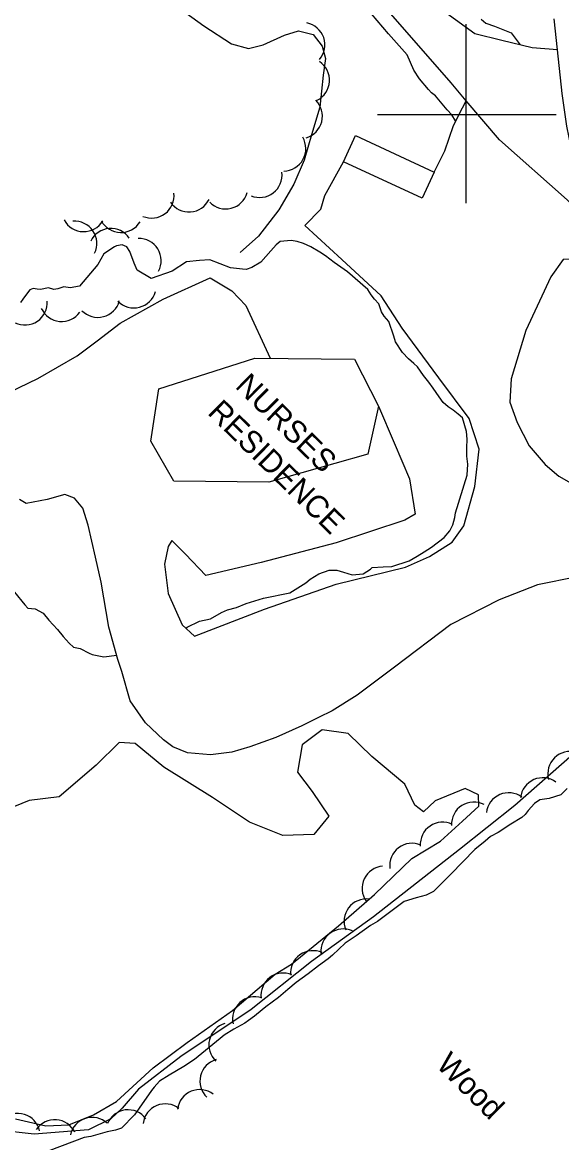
# Model space of a CAD drawing. Extents: x 642515 to 647219, y 6080136 to 6084356.
# Drawn here: x 643540.5 to 643612.9, y 6081462 to 6081612.4 of the extents above; entities that cross this region are included whole.
import ezdxf

# ---------------------------------------------------------------- set-up
doc = ezdxf.new("R2010")
doc.units = 0
for name, color, linetype in [('Level 19', 7, 'Continuous'), ('Level 2', 7, 'Continuous'), ('Level 21', 7, 'Continuous'), ('Level 31', 7, 'Continuous'), ('Level 4', 7, 'Continuous'), ('Level 44', 7, 'Continuous'), ('Level 61', 7, 'Continuous')]:
    doc.layers.add(name, color=color, linetype=linetype)

msp = doc.modelspace()

# ---------------------------------------------------------------- linework, layer by layer
at = {"layer": 'Level 19'}
for points in [[(643595.76, 6081592.33), (643597.18, 6081595.17), (643598.37, 6081598.59), (643599.58, 6081600.93), (643600.07, 6081601.9)], [(643588.29, 6081560.9), (643590.39, 6081555.97), (643592.44, 6081551.16), (643593.2, 6081546.42), (643591.8, 6081545.6), (643582.59, 6081542.57), (643572.51, 6081539.93), (643565.07, 6081538.15), (643562.38, 6081541.03), (643560.53, 6081542.88), (643560.02, 6081542.04), (643559.54, 6081539.67), (643560.04, 6081535.76), (643561.93, 6081531.54), (643563.56, 6081530.03), (643572.99, 6081533.64), (643582.59, 6081537.02), (643591.91, 6081539.29), (643595.12, 6081540.72), (643598.17, 6081542.65), (643599.72, 6081544.85), (643601.22, 6081550.11), (643601.82, 6081555.11), (643600.46, 6081559.25), (643596.39, 6081564.7), (643591.48, 6081571.35), (643588.65, 6081575.72), (643583.37, 6081580.57), (643578.4, 6081585.15), (643580.55, 6081587.35), (643581.07, 6081589.16), (643583.57, 6081593.71)], [(643618.02, 6081580.18), (643615.49, 6081580.74), (643613.08, 6081580.58), (643611.43, 6081578.25), (643608.07, 6081571.06), (643606.09, 6081564.56), (643605.93, 6081561.44), (643606.92, 6081558.69), (643608.5, 6081555.57), (643610.68, 6081553.05), (643612.51, 6081551.52), (643616.53, 6081549.21), (643619.17, 6081548.25), (643621.21, 6081547.99), (643624.04, 6081548.38), (643628.44, 6081549.43), (643630.6, 6081550.34), (643632.99, 6081551.81)], [(643537.52, 6081562.18), (643542.51, 6081564.6), (643547.81, 6081567.65), (643550.49, 6081569.68), (643553.6, 6081572.02), (643559.38, 6081575.26), (643565.66, 6081578.13), (643568.59, 6081576.39), (643570.45, 6081574.39), (643573.74, 6081567.33)], [(643614.95, 6081537.99), (643609.62, 6081536.91), (643604.48, 6081534.91), (643598.01, 6081531.58), (643590.42, 6081525.84), (643585.43, 6081522.12), (643582.06, 6081520), (643580.23, 6081519.12), (643577.97, 6081518), (643574.48, 6081516.44), (643571.02, 6081515.16), (643568.57, 6081514.43), (643565.7, 6081514.08), (643562.62, 6081514.36), (643560.67, 6081515.16), (643559.4, 6081516.12), (643557, 6081518.38), (643554.91, 6081521.34), (643553.8, 6081525.26), (643553.29, 6081526.91), (643552.08, 6081531.23), (643551.03, 6081537.28), (643550.25, 6081540.61), (643549.28, 6081544.93), (643548.56, 6081547.22), (643547.47, 6081548.55), (643546.15, 6081549.03), (643543.78, 6081548.39), (643540.96, 6081547.84), (643540.08, 6081548.38)]]:
    msp.add_lwpolyline(points, dxfattribs=at)
at = {"layer": 'Level 2'}
for points in [[(643598.65, 6081599.13), (643598.61, 6081599.18), (643598.11, 6081599.99), (643597.5, 6081600.67), (643595.93, 6081602.58), (643595.38, 6081602.98), (643594.99, 6081603.4), (643593.77, 6081604.85), (643593.04, 6081606), (643592.14, 6081608.07), (643589.62, 6081610.88), (643586.57, 6081614.45)], [(643602.06, 6081612.86), (643602.7, 6081612.3), (643603.85, 6081611.9), (643606.08, 6081611), (643607.29, 6081609.39)], [(643591.51, 6081568.1), (643590.57, 6081569.52), (643590.35, 6081570.31), (643589.65, 6081572.27), (643589.04, 6081572.96), (643588.68, 6081573.57), (643588.33, 6081574.64), (643587.76, 6081575.28), (643587.28, 6081575.85), (643586.83, 6081576.54), (643584.1, 6081578.93), (643582.32, 6081580.18), (643581.14, 6081581.07), (643580.38, 6081581.58), (643579.2, 6081582.3), (643578.21, 6081582.72), (643577.35, 6081583.02), (643576.54, 6081583.13), (643575.06, 6081582.99), (643574.53, 6081582.55), (643573.82, 6081581.74), (643572.48, 6081580.21), (643571.28, 6081579.52), (643570.49, 6081579.23), (643570.01, 6081579.28), (643568.39, 6081579.49), (643565.62, 6081580.55), (643564.26, 6081580.46), (643562.51, 6081580.26), (643560.58, 6081579.01), (643557.76, 6081578.02), (643555.87, 6081579.14), (643555.45, 6081580.11), (643554.9, 6081581.65), (643554.49, 6081582.3), (643553.87, 6081582.54), (643553.08, 6081582.41), (643552.81, 6081582.27), (643551.38, 6081581.33), (643550.6, 6081579.91), (643548.14, 6081577.02), (643546.87, 6081576.77), (643546.02, 6081576.91), (643545.19, 6081576.66), (643544.68, 6081576.58), (643543.94, 6081576.78), (643542.87, 6081576.58), (643542.42, 6081576.59), (643541.9, 6081576.68), (643541.46, 6081576.53), (643541.02, 6081575.94), (643540.51, 6081575.26)], [(643540.51, 6081575.26), (643540.18, 6081574.8)], [(643562.41, 6081531.1), (643562.6, 6081531.21), (643564.23, 6081532.04), (643565.7, 6081532.34), (643567.21, 6081533.2), (643567.98, 6081533.57), (643569.21, 6081533.86), (643570.5, 6081534.39), (643572.82, 6081535.14), (643576.35, 6081535.82), (643578.51, 6081537.17), (643579.12, 6081537.69), (643580.27, 6081538.41), (643581.65, 6081538.87), (643582.69, 6081538.86), (643583.6, 6081538.6), (643584.74, 6081538.27), (643586.22, 6081538.41), (643587.19, 6081539), (643587.45, 6081539.22), (643588.89, 6081539.31), (643590.09, 6081539.39), (643592.41, 6081540.15), (643593.46, 6081540.74), (643594.42, 6081541.33), (643595.42, 6081541.96), (643597.1, 6081543.28), (643597.88, 6081544.17), (643598.27, 6081544.96), (643598.53, 6081545.94), (643598.64, 6081546.59), (643600.19, 6081551.64), (643600.28, 6081553.13), (643600.13, 6081554.17), (643600.14, 6081555.29), (643600.18, 6081556.46), (643600.11, 6081557.5), (643599.54, 6081559.35), (643598.98, 6081559.84), (643598.3, 6081560.35), (643597.63, 6081560.79), (643596.95, 6081561.39), (643596.41, 6081562.16), (643595.61, 6081563.31), (643595.03, 6081564.11), (643594.33, 6081565.03), (643593.53, 6081566.18), (643593.01, 6081566.63), (643592.33, 6081567.23), (643591.51, 6081568.1)], [(643539.37, 6081535.92), (643540.77, 6081534.25), (643541.2, 6081533.8), (643542.17, 6081533.7), (643543.22, 6081533.09), (643544.01, 6081532.17), (643545.18, 6081530.93), (643545.93, 6081529.97), (643546.75, 6081529.1), (643547.31, 6081528.54), (643548.21, 6081528.36), (643549.41, 6081527.75), (643549.83, 6081527.54), (643551.38, 6081527.24), (643553.13, 6081527.47)], [(643550.01, 6081465.75), (643553.11, 6081467.56), (643558.03, 6081472.07), (643562.58, 6081475.46), (643568.68, 6081479.77), (643574.38, 6081484.65), (643576.58, 6081485.99), (643582.9, 6081491.15), (643587.76, 6081495.33), (643592.74, 6081500.16), (643596.6, 6081502.51), (643599.55, 6081505.19), (643601.75, 6081507.19), (643601.73, 6081508.71), (643599.9, 6081509.56), (643595.91, 6081507.93), (643594.32, 6081506.46), (643593.14, 6081507.34), (643591.82, 6081510.15), (643587.39, 6081513.88), (643584.21, 6081516.96), (643580.72, 6081517.45), (643578.05, 6081515.43), (643577.41, 6081511.77), (643579.35, 6081509.17), (643581.59, 6081505.86), (643579.58, 6081503.39), (643575.41, 6081503.28), (643570.95, 6081505.07), (643565.98, 6081508.36), (643559.44, 6081512.43), (643555.61, 6081515.63), (643553.43, 6081515.73), (643550.34, 6081512.71), (643545.4, 6081508.45), (643541.34, 6081507.94), (643536.41, 6081505.93)], [(643613.63, 6081509.56), (643612.76, 6081508.74), (643611.19, 6081508.24), (643609.95, 6081508.03), (643609.22, 6081507.54), (643608.4, 6081506.61), (643608, 6081506.06), (643607.54, 6081505.7), (643606.07, 6081504.8), (643604.34, 6081503.68), (643603.33, 6081503.14), (643602.61, 6081502.48), (643601.2, 6081501.39), (643598.01, 6081498.08), (643595.67, 6081495.76), (643594.7, 6081495.25)], [(643594.7, 6081495.25), (643593.32, 6081494.88), (643591.71, 6081494.41), (643588.15, 6081491.72), (643587.22, 6081491.18), (643585.27, 6081489.8), (643583.8, 6081488.82), (643582.1, 6081487.22), (643581.5, 6081486.7), (643580.23, 6081485.77), (643578.82, 6081484.67), (643577.21, 6081483.52), (643576.11, 6081482.6), (643574.85, 6081481.52), (643573.17, 6081480.28), (643572.64, 6081479.84), (643571.61, 6081479.01), (643570.8, 6081478.43), (643570.34, 6081478.08), (643568.87, 6081477.26), (643567.56, 6081476.45), (643567.03, 6081476.01), (643563.56, 6081473.17), (643562.14, 6081472.23), (643560.16, 6081471.1), (643558.85, 6081470.29), (643558.14, 6081469.48), (643557.81, 6081469.01), (643556.12, 6081466.65), (643555.5, 6081465.76), (643553.77, 6081463.96), (643552.94, 6081463.71), (643551.83, 6081463.47), (643549.63, 6081462.84), (643548.75, 6081462.7), (643542.48, 6081460.36)], [(643539.52, 6081465.22), (643543.6, 6081464.28), (643546.68, 6081464.44), (643550.01, 6081465.75)]]:
    msp.add_lwpolyline(points, dxfattribs=at)
at = {"layer": 'Level 21'}
for points in [[(643616.32, 6081586.09), (643616.32, 6081586.09), (643613.62, 6081588.61), (643604.55, 6081596.63), (643600.07, 6081601.9), (643598.04, 6081604.29), (643589.94, 6081613.58)], [(643612.33, 6081608.72), (643608.93, 6081608.98), (643604.83, 6081610), (643601.23, 6081610.88), (643597.34, 6081613.69)], [(643635.25, 6081548.28), (643632.99, 6081551.81), (643629.41, 6081557.4), (643623.45, 6081567.23), (643619.32, 6081576.06), (643618.02, 6081580.18), (643617.28, 6081582.53), (643616.32, 6081586.09), (643615.15, 6081590.89), (643613.56, 6081598.48), (643612.95, 6081602.87), (643612.33, 6081608.72), (643611.89, 6081612.88)]]:
    msp.add_lwpolyline(points, dxfattribs=at)
at = {"layer": 'Level 31'}
for points in [[(643594.14, 6081588.83), (643583.57, 6081593.71), (643585.19, 6081597.22), (643595.76, 6081592.33), (643594.14, 6081588.83)], [(643586.86, 6081554.46), (643573.54, 6081550.7), (643560.78, 6081550.82), (643557.7, 6081556.22), (643558.78, 6081563.24), (643571.65, 6081567.36), (643585.04, 6081567.21), (643588.29, 6081560.9), (643586.86, 6081554.46)]]:
    msp.add_lwpolyline(points, dxfattribs=at)
at = {"layer": 'Level 4'}
for points in [[(643561.6, 6081614.26), (643564.82, 6081611.97), (643568.53, 6081609.55), (643570.83, 6081608.9), (643572.77, 6081609.39), (643575.67, 6081610.71), (643577.53, 6081611.28), (643579.5, 6081610.77), (643580.73, 6081609.23), (643581.16, 6081607.57), (643580.87, 6081605.33), (643580.42, 6081601.02), (643579.3, 6081597.32), (643578.31, 6081593.94), (643576.91, 6081590.7), (643574.88, 6081587.26), (643572.17, 6081583.73), (643569.7, 6081581.51)], [(643614.35, 6081514.09), (643606.58, 6081507.28), (643599.15, 6081501.38), (643587.62, 6081492.35), (643579.28, 6081486.36), (643571.2, 6081479.89), (643561.75, 6081473.58), (643556.03, 6081469.21), (643553.87, 6081466.65), (643552.31, 6081465.22), (643549.35, 6081463.73), (643542.05, 6081463.16), (643537.22, 6081463.69)]]:
    msp.add_lwpolyline(points, dxfattribs=at)
at = {"layer": 'Level 44'}
for centre, start, end in [((643578.08, 6081609.4), 318.8461, 78.824), ((643578.7, 6081604.65), 296.445, 56.423), ((643577.75, 6081599.82), 285.7568, 45.7348), ((643575.52, 6081595.46), 270.8306, 30.8085), ((643572.32, 6081591.91), 247.3253, 7.3032), ((643557.82, 6081589.14), 246.9191, 6.897), ((643562.82, 6081589.96), 214.3025, 334.2805), ((643567.75, 6081590.37), 224.4751, 344.453), ((643548.69, 6081587.33), 208.6554, 328.6333), ((643547.45, 6081582.74), 334.2293, 94.2073), ((643553.69, 6081587.21), 208.6554, 328.6333), ((643552.34, 6081581.75), 34.5591, 154.5371), ((643556.09, 6081580.42), 331.7405, 91.7185), ((643555.42, 6081577.08), 224.5031, 344.4811), ((643540.78, 6081574.79), 244.0508, 4.0288), ((643545.72, 6081575.27), 204.54, 324.518), ((643550.58, 6081575.82), 224.5031, 344.4811), ((643614.02, 6081511.54), 74.3265, 194.3044), ((643610.34, 6081508.01), 53.6614, 173.6394), ((643605.76, 6081506), 53.6614, 173.6394), ((643601.08, 6081504.75), 62.4138, 182.3917), ((643596.89, 6081502.05), 64.2776, 184.2555), ((643592.78, 6081499.22), 67.0292, 187.0071), ((643589.08, 6081496.16), 94.6229, 214.6009), ((643586.65, 6081491.74), 82.4308, 202.4087), ((643583.54, 6081487.72), 65.7558, 185.7338), ((643579.48, 6081484.8), 65.7558, 185.7338), ((643575.49, 6081481.8), 67.1474, 187.1253), ((643571.68, 6081478.62), 72.5475, 192.5255), ((643568.49, 6081475.14), 106.2522, 226.2301), ((643567.3, 6081470.29), 106.2522, 226.2301), ((643564.26, 6081466.15), 52.5312, 172.5091), ((643559.64, 6081464.23), 52.5312, 172.5091), ((643539.83, 6081462.95), 12.8898, 132.8677), ((643549.82, 6081462.43), 47.3588, 167.3367), ((643554.64, 6081463.44), 37.0254, 157.0034), ((643544.8, 6081462.11), 25.8889, 145.8669)]:
    msp.add_arc(centre, 3, start, end, dxfattribs=at)
at = {"layer": 'Level 61'}
for p, q in [((643600, 6081612.16), (643600, 6081588.16)), ((643612.16, 6081600), (643588.16, 6081600))]:
    msp.add_line(p, q, dxfattribs=at)

# ---------------------------------------------------------------- texts
at = {"layer": 'Level 31'}
for s, p in [('NURSES', (643568.89, 6081563.45)), ('RESIDENCE', (643565.19, 6081559.9))]:
    msp.add_text(s, height=3, rotation=315.5629, dxfattribs=at).set_placement(p)
at = {"layer": 'Level 44'}
msp.add_text('Wood', height=3, rotation=315.1749, dxfattribs=at).set_placement((643595.88, 6081472.31))

doc.saveas('drawing.dxf')
